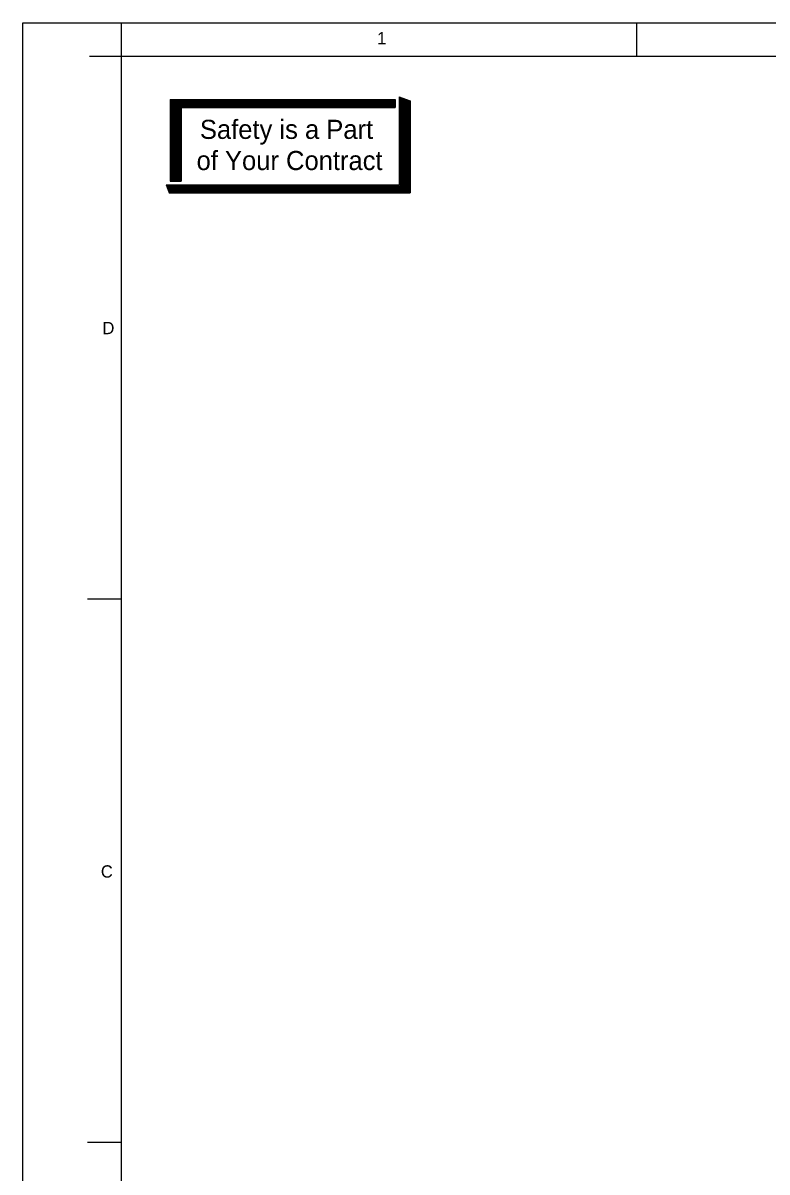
# Model space of a CAD drawing. Extents: x 22339.2 to 22413.4, y 22369.6 to 22418.8.
# Drawn here: x 22354.72 to 22369.8, y 22391.69 to 22414.97 of the extents above; entities that cross this region are included whole.
import ezdxf

# ---------------------------------------------------------------- set-up
doc = ezdxf.new("R2010")
doc.units = 0
for name, color, linetype in [('Level 1', 7, 'Continuous'), ('Level 10', 7, 'Continuous'), ('Level 9', 7, 'Continuous')]:
    doc.layers.add(name, color=color, linetype=linetype)

msp = doc.modelspace()

# ---------------------------------------------------------------- linework, layer by layer
at = {"layer": 'Level 1'}
msp.add_lwpolyline([(22354.719, 22414.965), (22413.386, 22414.965), (22413.386, 22369.621), (22354.719, 22369.621)], close=True, dxfattribs=at)
at = {"layer": 'Level 10'}
for p, q in [((22356.719, 22414.293), (22356.719, 22414.965)), ((22367.162, 22414.293), (22367.162, 22414.965)), ((22356.068, 22414.293), (22356.712, 22414.293)), ((22357.705, 22413.418), (22362.261, 22413.418)), ((22357.705, 22413.418), (22357.705, 22411.764)), ((22357.705, 22413.397), (22362.261, 22413.397)), ((22357.705, 22413.377), (22362.261, 22413.377)), ((22357.705, 22413.356), (22362.261, 22413.356)), ((22357.705, 22413.334), (22362.261, 22413.334)), ((22357.705, 22413.314), (22362.261, 22413.314)), ((22357.705, 22413.293), (22362.261, 22413.293)), ((22357.705, 22413.273), (22362.261, 22413.273)), ((22357.726, 22413.418), (22357.726, 22411.764)), ((22357.746, 22413.418), (22357.746, 22411.764)), ((22357.768, 22413.418), (22357.768, 22411.764)), ((22357.788, 22413.418), (22357.788, 22411.764)), ((22357.809, 22413.418), (22357.809, 22411.764)), ((22357.83, 22413.418), (22357.83, 22411.764)), ((22357.85, 22413.418), (22357.85, 22411.764)), ((22357.872, 22413.418), (22357.872, 22411.764)), ((22357.893, 22413.418), (22357.893, 22411.764)), ((22357.913, 22413.418), (22357.913, 22411.764)), ((22357.928, 22413.252), (22362.261, 22413.252)), ((22357.928, 22413.252), (22357.928, 22411.764)), ((22362.261, 22413.418), (22362.261, 22413.252)), ((22362.345, 22413.468), (22362.345, 22411.689)), ((22362.345, 22413.468), (22362.568, 22413.385)), ((22362.36, 22413.462), (22362.36, 22411.522)), ((22362.38, 22413.454), (22362.38, 22411.522)), ((22362.401, 22413.446), (22362.401, 22411.522)), ((22362.422, 22413.438), (22362.422, 22411.522)), ((22362.442, 22413.432), (22362.442, 22411.522)), ((22362.464, 22413.424), (22362.464, 22411.522)), ((22362.484, 22413.416), (22362.484, 22411.522)), ((22362.505, 22413.408), (22362.505, 22411.522)), ((22362.526, 22413.401), (22362.526, 22411.522)), ((22362.546, 22413.385), (22362.546, 22411.522)), ((22362.568, 22413.385), (22362.568, 22411.522)), ((22357.621, 22411.689), (22362.345, 22411.689)), ((22357.621, 22411.689), (22357.682, 22411.522)), ((22357.629, 22411.668), (22362.36, 22411.668)), ((22357.636, 22411.648), (22362.36, 22411.648)), ((22357.644, 22411.626), (22362.36, 22411.626)), ((22357.705, 22411.764), (22357.928, 22411.764)), ((22357.652, 22411.605), (22362.36, 22411.605)), ((22357.66, 22411.585), (22362.36, 22411.585)), ((22357.668, 22411.564), (22362.36, 22411.564)), ((22357.674, 22411.544), (22362.36, 22411.544)), ((22357.682, 22411.522), (22362.568, 22411.522)), ((22356.026, 22403.301), (22356.698, 22403.301)), ((22356.026, 22392.293), (22356.698, 22392.293))]:
    msp.add_line(p, q, dxfattribs=at)
at = {"layer": 'Level 9'}
for p, q in [((22356.719, 22370.293), (22356.719, 22414.293)), ((22356.719, 22414.293), (22409.05, 22414.293))]:
    msp.add_line(p, q, dxfattribs=at)

# ---------------------------------------------------------------- texts
at = {"layer": 'Level 1'}
for s, p in [('1', (22361.898, 22414.533)), ('D', (22356.33, 22408.661)), ('C', (22356.298, 22397.653))]:
    msp.add_text(s, height=0.25, dxfattribs=at).set_placement(p)
at = {"layer": 'Level 10'}
for s, p in [('Safety is a Part', (22358.305, 22412.617)), ('of Your Contract', (22358.237, 22411.986))]:
    msp.add_text(s, height=0.38717, dxfattribs=at).set_placement(p)

doc.saveas('drawing.dxf')
